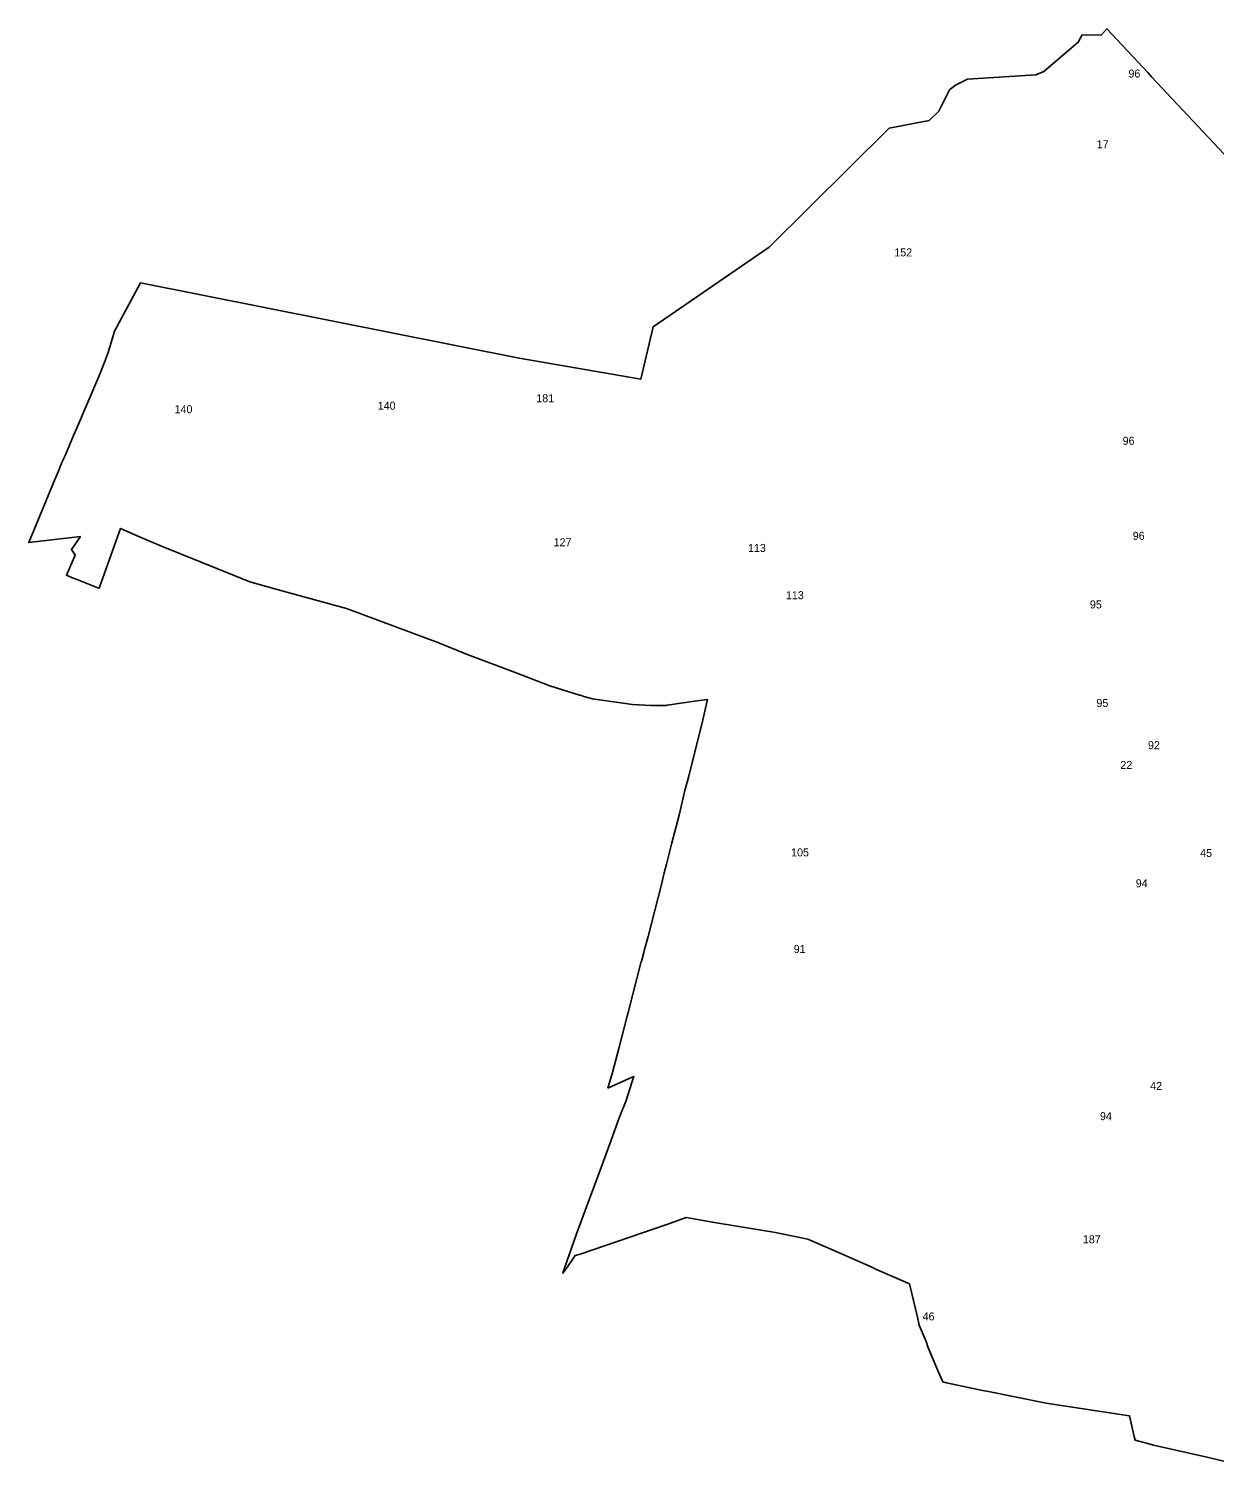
# Model space of a CAD drawing. Extents: x -783397 to -779545, y -982643 to -979975.
# Drawn here: x -783397 to -781470, y -982579 to -980248 of the extents above; entities that cross this region are included whole.
import ezdxf

# ---------------------------------------------------------------- set-up
doc = ezdxf.new("R2010")
doc.units = 0
for name, color, linetype in [('Vrstva 22', 7, 'Continuous'), ('Vrstva 24', 7, 'Continuous'), ('Vrstva 28', 7, 'Continuous')]:
    doc.layers.add(name, color=color, linetype=linetype)

msp = doc.modelspace()

# ---------------------------------------------------------------- linework, layer by layer
at = {"layer": 'Vrstva 22'}
for points in [[(-781965.37, -982287.186), (-782022.981, -982262.496), (-782023.055, -982261.933), (-782076.911, -982238.014), (-782130.908, -982214.858), (-782172.883, -982206.023), (-782183.155, -982203.969), (-782242.733, -982193.844), (-782285.876, -982187.24), (-782328.666, -982179.304), (-782359.771, -982190.579), (-782501.005, -982239.188), (-782509.223, -982241.242), (-782522.576, -982260.906), (-782528.996, -982270.091), (-782526.253, -982261.446), (-782507.004, -982206.148), (-782463.144, -982087.747), (-782448.177, -982047.832), (-782437.318, -982017.309), (-782426.311, -981989.134), (-782416.63, -981960.218), (-782413.468, -981950.125), (-782421.176, -981953.475), (-782455.849, -981969.216), (-782448.177, -981943.643), (-782437.712, -981902.726), (-782424.257, -981852.074), (-782422.239, -981844.212), (-782401.452, -981763.23), (-782400.778, -981762.706), (-782400.778, -981761.385), (-782397.256, -981748.765), (-782396.375, -981744.069), (-782390.506, -981722.938), (-782369.374, -981640.761), (-782364.385, -981619.629), (-782360.276, -981605.542), (-782352.352, -981572.671), (-782340.172, -981525.712), (-782330.633, -981485.798), (-782324.177, -981462.318), (-782301.431, -981371.043), (-782293.855, -981337.995), (-782302.605, -981338.905), (-782314.825, -981340.431), (-782359.249, -981346.976), (-782360.717, -981347.564), (-782385.663, -981347.27), (-782415.893, -981345.656), (-782481.048, -981336.557), (-782495.135, -981332.742), (-782500.418, -981330.834), (-782502.179, -981330.688), (-782550.312, -981315.426), (-782609.01, -981292.68), (-782683.002, -981265.022), (-782734.917, -981244.108), (-782751.353, -981238.385), (-782880.782, -981189.665), (-782983.504, -981161.931), (-783037.506, -981146.522), (-783116.743, -981114.491), (-783181.316, -981088.411), (-783216.829, -981073.736), (-783247.859, -981059.883), (-783250.14, -981066.106), (-783282.57, -981157.088), (-783285.065, -981156.208), (-783308.985, -981146.816), (-783317.203, -981143.147), (-783327.475, -981139.479), (-783335.758, -981135.651), (-783321.566, -981103.023), (-783327.833, -981093.845), (-783313.116, -981073.144), (-783397.199, -981082.81), (-783354.769, -980980.113), (-783347.579, -980964.265), (-783343.617, -980953.699), (-783340.975, -980948.416), (-783340.241, -980945.775), (-783337.6, -980940.492), (-783324.539, -980908.795), (-783319.55, -980898.229), (-783284.772, -980816.639), (-783280.369, -980806.367), (-783268.619, -980775.575), (-783261.524, -980752.306), (-783257.774, -980739.373), (-783215.42, -980660.76)], [(-781441.504, -982578.756), (-781479.658, -982569.512), (-781568.879, -982549.261), (-781578.27, -982546.766), (-781598.704, -982541.314), (-781600.282, -982535.32), (-781607.758, -982501.661), (-781665.29, -982493.204), (-781743.421, -982481.07), (-781839.771, -982461.507), (-781844.467, -982460.92), (-781905.513, -982448.007), (-781911.529, -982446.392), (-781918.573, -982430.838), (-781935.889, -982389.749), (-781938.53, -982380.944), (-781950.032, -982354.216), (-781952.765, -982341.323), (-781965.37, -982287.186)]]:
    msp.add_lwpolyline(points, dxfattribs=at)
at = {"layer": 'Vrstva 28'}
for points in [[(-783215.42, -980660.76), (-783215.42, -980660.76), (-782600.26, -980783.45), (-782402.44, -980817.39), (-782382.36, -980732.11), (-782193.48, -980602.73), (-781998.4, -980409.65), (-781933.82, -980396.83), (-781917.64, -980382.17), (-781900.77, -980347.33), (-781891.03, -980339.71), (-781871.34, -980329.76), (-781760.18, -980322.93), (-781747.25, -980317.7), (-781691.18, -980269.87), (-781684.89, -980257.96), (-781653.96, -980258.17), (-781644.7, -980247.91), (-781578.2, -980319.22)], [(-781578.2, -980319.22), (-781574.37, -980323.17)], [(-781574.37, -980323.17), (-781571.99, -980326.21)], [(-781571.99, -980326.21), (-781235.28, -980684.54)]]:
    msp.add_lwpolyline(points, dxfattribs=at)

# ---------------------------------------------------------------- texts
at = {"layer": 'Vrstva 24'}
for s, p in [('96', (-781609.725, -980327.274)), ('17', (-781661.191, -980442.068)), ('152', (-781990.27, -980617.842)), ('181', (-782572.086, -980854.875)), ('140', (-783160.093, -980872.637)), ('140', (-782829.839, -980866.924)), ('96', (-781619.155, -980923.904)), ('127', (-782544.038, -981088.856)), ('96', (-781602.735, -981078.304)), ('113', (-782228.018, -981098.031)), ('113', (-782166.444, -981174.799)), ('95', (-781672.361, -981189.854)), ('95', (-781661.751, -981349.994)), ('92', (-781577.991, -981418.504)), ('22', (-781622.863, -981450.622)), ('105', (-782158.016, -981592.664)), ('45', (-781493.11, -981593.634)), ('94', (-781597.829, -981642.904)), ('91', (-782153.811, -981749.624)), ('42', (-781574.351, -981972.032)), ('94', (-781656.019, -982021.284)), ('187', (-781683.769, -982221.332)), ('46', (-781944.246, -982346.57))]:
    msp.add_text(s, height=13, dxfattribs=at).set_placement(p)

doc.saveas('drawing.dxf')
